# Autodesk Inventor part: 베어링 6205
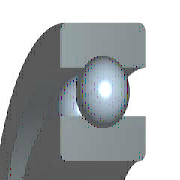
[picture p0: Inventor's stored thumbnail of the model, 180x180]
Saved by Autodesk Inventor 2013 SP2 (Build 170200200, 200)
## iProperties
IsCustomPart: 1
Company: 한국ATC센터
Created: 2014-11
Part Number: 베어링 6205
Material: 강, 연강
Description: 깊은 그루브 볼 베어링
Document SubType Name: Modeling
Standard: KS B 2023
Designer: KYOUNG IL JANG
Standards Organization: KS
Language: ko-KR
Size Designation: 6205 - 25 x 52 x 15
Categories: <MemberInstance><Categories><Category DisplayName="샤프트 부품" InternalName="7f7aeb1f-a693-4053-b835-cee3144e0d98" Mnemonic="SHFT"><Category DisplayName="베어링" Inter
Density: 7.86 g/cm^3
Mass: 129.543 g
Surface Area: 107.326 cm^2
Volume: 16.4813 cm^3
Author: KYOUNG IL JANG
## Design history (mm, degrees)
sketch "스케치" dims "d0" = 7.02 (= -0.26 x WD + 0.26 x BD)
  geometry: L1 (3.99, 19.25)-(11.01, 19.25); L2 (7.5, 19.25)-(7.5, 15.74); L3 (7.5, 19.25)-(7.5, 22.76); L4 (4.892, 16.901)-(0, 16.901); L5 (0, 12.5)-(15, 12.5); L6 (4.892, 21.599)-(0, 21.599); L7 (0, 26)-(15, 26); L8 (15, 12.5)-(15, 16.901); L9 (10.108, 16.901)-(15, 16.901); L10 (10.108, 21.599)-(15, 21.599); L11 (15, 26)-(15, 21.599); L12 (-1.4, 0)-(8.4, 0) reference; L13 (0, -0.3)-(0, 5.3) reference
  constraints: 22 end point, 4 point on line, 2 collinear, 2 perpendicular, 2 symmetric about line, 1 midpoint, 1 parallel, 14 other
  dimensions: "d9" = 25 diameter of L5 L12 (= WD); "d11" = 52 diameter of L7 L12 (= BD); "d12" = 15 distance between parallel lines of L8 L13 (= KB); "d13" = 33.802 diameter of L9 L12 (= 0.326 x BD + 0.674 x WD)
revolve "본체" stored, may be unused: angle "d6" = 90 deg
revolve "볼" stored, may be unused: angle "d7" = 90 deg
pattern_circular "IDS_ARRAYBALL[SIMPL:T]" dims angle "d3" = 360 deg
body "Solid1"
fillet "모깎기1" dims "d1" = 1 (= KRS)
other parameters: "WD" = 25 [user parameter; used in 5 equation terms], "BD" = 52 [user parameter; used in 5 equation terms], "KB" = 15 [user parameter; used in 1 equation term], "KRS" = 1 [user parameter; used in 1 equation term], "d4" = 0, "d5" = 0, "d8" = 0, "d14" = 0, "d15" = 0, "BBA" = 0 [user parameter], "BC0" = 7800000 [user parameter], "BC" = 1.4e+07 [user parameter], "BR" = 26 (= 0.5 x BD) [user parameter], "WR" = 12.5 (= 0.5 x WD) [user parameter]
